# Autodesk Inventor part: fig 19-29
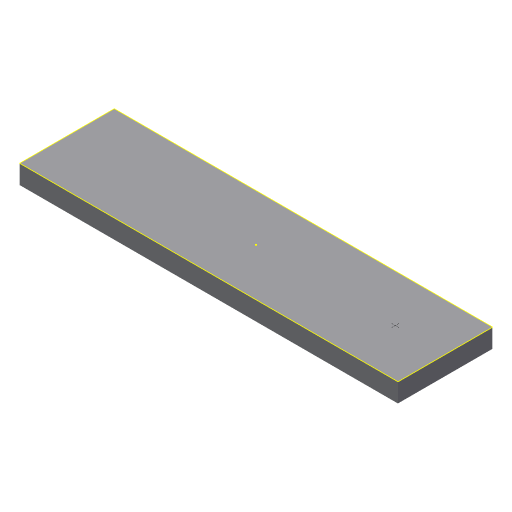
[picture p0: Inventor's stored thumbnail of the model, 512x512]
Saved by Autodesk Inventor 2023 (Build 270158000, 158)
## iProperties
Created: 2013-07
Part Number: fig 19-29
Material: Generic
Document SubType Name: Modeling
Designer: CADCIM
Density: 1 g/cm^3
Appearance: Default
Author: CADCIM
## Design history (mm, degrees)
sketch "Sketch1"
  geometry: L1 (-20, 5)-(20, 5); L2 (20, 5)-(20, -5); L3 (20, -5)-(-20, -5); L4 (-20, -5)-(-20, 5); L5 (-20, 5)-(20, -5); L6 (20, 5)-(-20, -5); 1 further point
  constraints: 12 end point, 2 midpoint, 2 parallel, 1 horizontal, 1 perpendicular
  dimensions: "d0" = 40 distance of L2.end L3.end; "d1" = 10 distance of L1.end L2.end
extrude "Extrusion1" new body sketch "Sketch1" distance "d2" = 2; taper "d3" = 0 deg
sketch "Sketch2"
  geometry: L1 (20, 5)-(-20, 5) reference; L2 (-20, 5)-(-20, -5) reference; L3 (-20, -5)-(20, -5) reference; L4 (20, -5)-(20, 5) reference; 2 further points
body "Solid1"
